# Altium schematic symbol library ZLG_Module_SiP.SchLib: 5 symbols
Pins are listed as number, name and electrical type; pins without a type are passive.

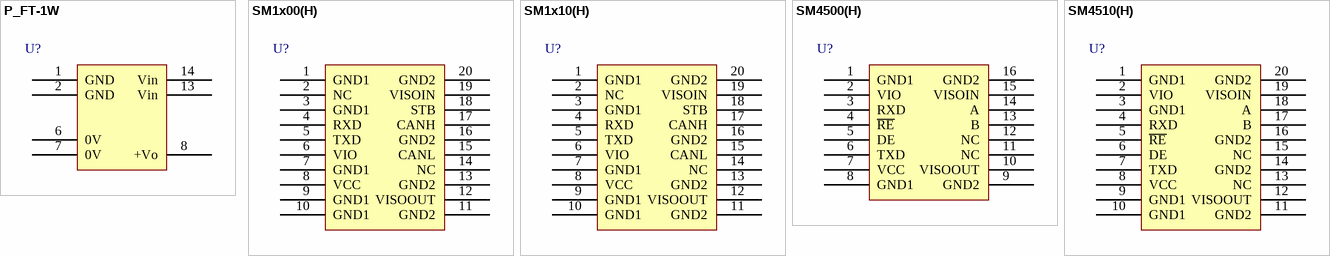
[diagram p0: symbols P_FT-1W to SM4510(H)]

## P_FT-1W
designator U?
footprint P_FT-1W
pins: 1 GND, 2 GND, 6 0V, 7 0V, 8 +Vo, 13 Vin, 14 Vin

## SM1x00(H)
designator U?
footprint SM1x00(H)
pins: 1 GND1, 2 NC, 3 GND1, 4 RXD, 5 TXD, 6 VIO, 7 GND1, 8 VCC, 9 GND1, 10 GND1, 11 GND2, 12 VISOOUT, 13 GND2, 14 NC, 15 CANL, 16 GND2, 17 CANH, 18 STB, 19 VISOIN, 20 GND2

## SM1x10(H)
designator U?
footprint SM1x10(H)
pins: 1 GND1, 2 NC, 3 GND1, 4 RXD, 5 TXD, 6 VIO, 7 GND1, 8 VCC, 9 GND1, 10 GND1, 11 GND2, 12 VISOOUT, 13 GND2, 14 NC, 15 CANL, 16 GND2, 17 CANH, 18 STB, 19 VISOIN, 20 GND2

## SM4500(H)
designator U?
footprint SM4500(H)
pins: 1 GND1, 2 VIO, 3 RXD, 4 ~{RE}, 5 DE, 6 TXD, 7 VCC, 8 GND1, 9 GND2, 10 VISOOUT, 11 NC, 12 NC, 13 B, 14 A, 15 VISOIN, 16 GND2

## SM4510(H)
designator U?
footprint SM4510(H)
pins: 1 GND1, 2 VIO, 3 GND1, 4 RXD, 5 ~{RE}, 6 DE, 7 TXD, 8 VCC, 9 GND1, 10 GND1, 11 GND2, 12 VISOOUT, 13 NC, 14 GND2, 15 NC, 16 GND2, 17 B, 18 A, 19 VISOIN, 20 GND2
